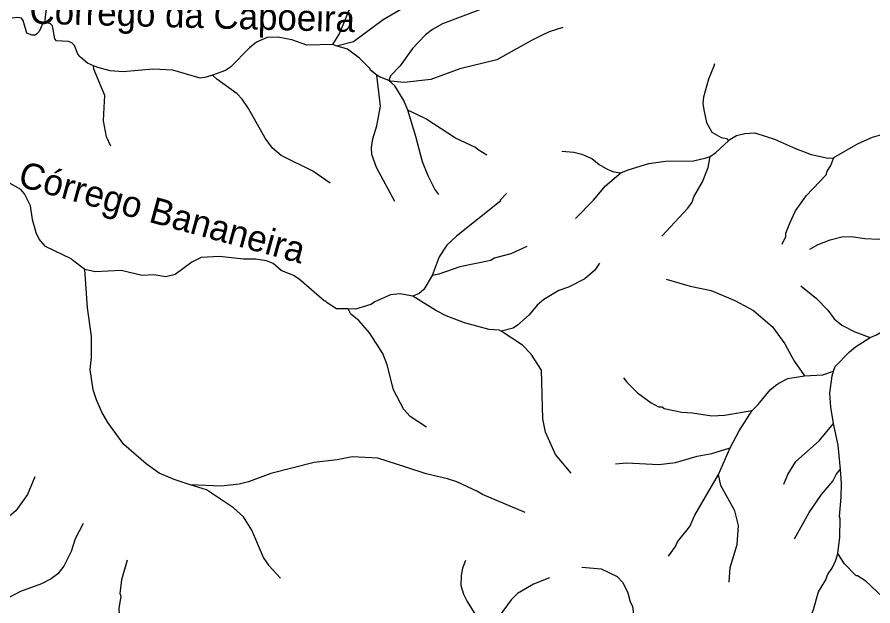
# Model space of a CAD drawing. Extents: x 393 to 446.6, y 8175.5 to 8231.
# Drawn here: x 415.52 to 420.77, y 8185.96 to 8189.58 of the extents above; entities that cross this region are included whole.
import ezdxf
from ezdxf.enums import TextEntityAlignment as Align

# ---------------------------------------------------------------- set-up
doc = ezdxf.new("R2010")
doc.units = 0
doc.header["$LTSCALE"] = 0.064
doc.linetypes.add('LONG_DASHED', pattern=[7.5, 6, -1.5])
doc.layers.add('61', color=7, linetype='Continuous')
doc.layers.add('7', color=7, linetype='Continuous', lineweight=25)
doc.layers.add('9', color=7, linetype='LONG_DASHED', lineweight=25)

msp = doc.modelspace()

# ---------------------------------------------------------------- linework, layer by layer
at = {"layer": '7'}
msp.add_line((419.8216, 8186.7653), (419.8938, 8186.9294), dxfattribs=at)
for points in [[(420.5309, 8188.7124), (420.6804, 8188.7995), (420.7676, 8188.8383), (421.0405, 8188.9158), (421.1244, 8188.9658), (421.1583, 8189.0159), (421.1729, 8189.0676), (421.1712, 8189.1903), (421.1793, 8189.2485), (421.2229, 8189.3421), (421.2423, 8189.3583), (421.2827, 8189.3776), (421.3678, 8189.3867)], [(419.7982, 8189.2882), (419.7926, 8189.2738), (419.7615, 8189.1936), (419.7292, 8189.0838), (419.726, 8189.045), (419.7325, 8189.0063), (419.7486, 8188.9287), (419.7809, 8188.869), (419.8391, 8188.8367), (419.8713, 8188.8302), (419.8827, 8188.8153)], [(419.8827, 8188.8153), (419.8911, 8188.8229), (419.9327, 8188.848), (419.9844, 8188.8609), (420.0441, 8188.8641), (420.115, 8188.8414), (420.1653, 8188.8254), (420.2944, 8188.7672), (420.3913, 8188.7317), (420.4947, 8188.7091), (420.5291, 8188.7113), (420.5309, 8188.7124)], [(419.7704, 8188.7194), (419.8051, 8188.7446), (419.8827, 8188.8153)], [(418.8595, 8188.7509), (418.9332, 8188.7463), (418.9832, 8188.7333), (419.0446, 8188.7059), (419.0898, 8188.6704), (419.1415, 8188.6397), (419.1802, 8188.6251), (419.2214, 8188.6181)], [(419.2214, 8188.6181), (419.2674, 8188.6381), (419.3934, 8188.6768), (419.4967, 8188.6897), (419.6679, 8188.693), (419.7454, 8188.7107), (419.7704, 8188.7194)], [(419.4748, 8188.23), (419.634, 8188.4023), (419.6598, 8188.4394), (419.6711, 8188.4717), (419.7228, 8188.5638), (419.7583, 8188.651), (419.7704, 8188.7194)], [(420.2133, 8188.1797), (420.2347, 8188.2279), (420.2363, 8188.2473), (420.2589, 8188.3087), (420.2944, 8188.3862), (420.3606, 8188.4766), (420.4834, 8188.6074), (420.4882, 8188.6284), (420.5124, 8188.6639), (420.5309, 8188.7123), (420.5309, 8188.7124)], [(420.383, 8188.1491), (420.4333, 8188.1779), (420.5076, 8188.2069), (420.5786, 8188.2247), (420.6368, 8188.2279), (420.7207, 8188.215), (420.8047, 8188.2117), (420.8564, 8188.2182), (420.9274, 8188.2505), (420.9791, 8188.2973), (421.0276, 8188.3248), (421.1567, 8188.3603), (421.1971, 8188.3845), (421.2601, 8188.4637), (421.2843, 8188.5121), (421.2988, 8188.5993), (421.3198, 8188.6381), (421.3441, 8188.6607), (421.3796, 8188.6736), (421.4715, 8188.6921), (421.4745, 8188.6927)], [(418.9446, 8188.3386), (419.0543, 8188.4507), (419.1285, 8188.5396), (419.2214, 8188.6181)], [(419.5012, 8187.9648), (419.6485, 8187.9227), (419.7777, 8187.8952), (419.923, 8187.8339), (420.0361, 8187.7725), (420.1539, 8187.6724), (420.2282, 8187.5675), (420.2717, 8187.4888), (420.288, 8187.4593), (420.35, 8187.3713)], [(420.328, 8187.924), (420.4236, 8187.8468), (420.493, 8187.7742), (420.5318, 8187.7225), (420.5786, 8187.6821), (420.6594, 8187.6417), (420.7534, 8187.608)], [(420.7534, 8187.608), (420.7918, 8187.6232), (420.8828, 8187.6759)], [(420.528, 8187.3995), (420.5381, 8187.4297), (420.6271, 8187.519), (420.6626, 8187.5497), (420.7534, 8187.608)], [(420.35, 8187.3713), (420.4624, 8187.3785), (420.5276, 8187.3994), (420.528, 8187.3995)], [(420.527, 8187.0789), (420.5124, 8187.1783), (420.5059, 8187.2655), (420.5189, 8187.3721), (420.528, 8187.3995)], [(419.239, 8187.36), (419.2594, 8187.3317), (419.3256, 8187.2671), (419.4095, 8187.2057), (419.4531, 8187.1815), (419.4757, 8187.1815), (419.4886, 8187.1718), (419.5969, 8187.1476), (419.6614, 8187.1444), (419.7809, 8187.125), (419.8584, 8187.1298), (420.028, 8187.1578)], [(420.028, 8187.1578), (420.0664, 8187.1962), (420.141, 8187.2881), (420.1803, 8187.3175), (420.1927, 8187.3268), (420.2476, 8187.3543), (420.35, 8187.3713)], [(419.8938, 8186.9294), (419.9488, 8187.033), (420.028, 8187.1578)], [(420.2232, 8186.7057), (420.2476, 8186.7649), (420.296, 8186.8456), (420.4398, 8186.9716), (420.527, 8187.0789)], [(420.57, 8186.7965), (420.5576, 8186.9458), (420.527, 8187.0789)], [(419.1892, 8186.8314), (419.2579, 8186.8372), (419.4547, 8186.8263), (419.5581, 8186.8392), (419.6905, 8186.8779), (419.7809, 8186.8941), (419.8938, 8186.9294)], [(419.5147, 8186.2636), (419.5581, 8186.3241), (419.5694, 8186.3515), (419.6469, 8186.4452), (419.676, 8186.5162), (419.8216, 8186.7653)], [(419.8882, 8186.1042), (419.8939, 8186.1933), (419.9359, 8186.3354), (419.944, 8186.4517), (419.9214, 8186.5421), (419.8358, 8186.6971), (419.8216, 8186.7653)], [(420.2884, 8186.3697), (420.3784, 8186.5324), (420.4543, 8186.6422), (420.5237, 8186.7245), (420.5447, 8186.7649), (420.5697, 8186.7961), (420.57, 8186.7965)], [(420.5543, 8186.281), (420.5673, 8186.3806), (420.5689, 8186.4936), (420.5641, 8186.5082), (420.5754, 8186.626), (420.577, 8186.7132), (420.57, 8186.7965)], [(415.6246, 8186.7521), (415.5792, 8186.6422), (415.5082, 8186.5421), (415.3887, 8186.4435), (415.3063, 8186.358), (415.1773, 8186.1552)], [(415.9215, 8186.4638), (415.8731, 8186.3709), (415.8473, 8186.2934), (415.8021, 8186.203), (415.7649, 8186.1561), (415.7246, 8186.1238), (415.6664, 8186.0931), (415.5373, 8186.0463), (415.4501, 8186.0011), (415.3629, 8185.972), (415.2854, 8185.9623), (415.1174, 8185.972), (415.0765, 8185.964)], [(416.1918, 8186.2392), (416.1573, 8186.1174), (416.1476, 8186.0512), (416.146, 8186.035), (416.1525, 8186.0173), (416.1412, 8185.9414), (416.1476, 8185.7864), (416.1379, 8185.7088), (416.104, 8185.5926), (416.0911, 8185.5667), (416.019, 8185.4685), (416.0187, 8185.4681)], [(420.3842, 8185.4635), (420.3558, 8185.5441), (420.3461, 8185.641), (420.3477, 8185.6943), (420.3752, 8185.8187), (420.3752, 8185.8541), (420.4058, 8185.9365), (420.4365, 8186.0447), (420.4817, 8186.119), (420.4914, 8186.1481), (420.5221, 8186.1949), (420.5415, 8186.2401), (420.5543, 8186.281)], [(421.0637, 8186.0792), (421.0404, 8186.0334), (420.9969, 8185.9849), (420.9371, 8185.9591), (420.8951, 8185.9672), (420.8289, 8186.014), (420.7255, 8186.1093), (420.6755, 8186.1432), (420.6674, 8186.1432), (420.5964, 8186.2175), (420.5543, 8186.281)]]:
    msp.add_lwpolyline(points, dxfattribs=at)
at = {"layer": '9'}
msp.add_line((417.4817, 8189.3978), (417.4516, 8189.4067), dxfattribs=at)
for points in [[(416.071, 8190.339), (416.0439, 8190.3239), (416.0065, 8190.2107), (415.9522, 8190.1754), (415.9119, 8190.1172), (415.9135, 8190.0494), (415.9054, 8190.0155), (415.8182, 8189.9428), (415.8085, 8189.8992), (415.7472, 8189.8201), (415.7455, 8189.7975), (415.7713, 8189.7849), (415.7713, 8189.7639), (415.7573, 8189.7371), (415.7095, 8189.6799), (415.6966, 8189.6426), (415.6861, 8189.5586), (415.6889, 8189.5437)], [(417.9643, 8190.06), (417.9619, 8190.0567), (417.911, 8189.9848), (417.8173, 8189.8911), (417.6219, 8189.7232), (417.5654, 8189.6457), (417.4945, 8189.4761), (417.4516, 8189.4067)], [(418.2612, 8189.9581), (418.2191, 8189.8742), (418.1853, 8189.8333), (418.1211, 8189.7738), (418.0657, 8189.7476), (417.9839, 8189.6904), (417.7624, 8189.5585), (417.5813, 8189.4237), (417.4843, 8189.3985), (417.4817, 8189.3978)], [(418.5923, 8189.7154), (418.5877, 8189.7134), (418.3987, 8189.6311), (418.3599, 8189.6215), (418.1274, 8189.5343), (418.066, 8189.4987), (418.0224, 8189.4665), (417.9433, 8189.3825), (417.8672, 8189.2751), (417.8089, 8189.2156), (417.7981, 8189.1861)], [(415.6889, 8189.5437), (415.6738, 8189.5382), (415.6503, 8189.4875), (415.6357, 8189.4713), (415.6261, 8189.4648), (415.6083, 8189.4648), (415.5744, 8189.4761), (415.5534, 8189.5536), (415.5421, 8189.5682), (415.5179, 8189.573), (415.486, 8189.5685)], [(415.9857, 8189.2768), (415.9472, 8189.2924), (415.9064, 8189.3263), (415.9019, 8189.3321), (415.8892, 8189.3486), (415.868, 8189.4017), (415.8521, 8189.418), (415.8321, 8189.4259), (415.7568, 8189.4293), (415.748, 8189.4418), (415.7334, 8189.5219), (415.7217, 8189.5347), (415.6889, 8189.5437)], [(418.8661, 8189.5121), (418.7814, 8189.4842), (418.7398, 8189.4643), (418.6732, 8189.4325), (418.46, 8189.313), (418.234, 8189.2581), (418.0563, 8189.1919), (417.8916, 8189.1742), (417.8094, 8189.1818), (417.7981, 8189.1861)], [(417.4516, 8189.4067), (417.2946, 8189.4038), (417.2018, 8189.4358), (417.1165, 8189.4519), (417.0519, 8189.4503), (416.9857, 8189.4212), (416.9421, 8189.3873), (416.8259, 8189.2678), (416.7952, 8189.2468), (416.716, 8189.2197)], [(417.7247, 8189.2197), (417.6849, 8189.2501), (417.6817, 8189.2598), (417.6171, 8189.3227), (417.5444, 8189.3793), (417.4817, 8189.3978)], [(416.0909, 8188.782), (416.0653, 8188.8399), (416.0459, 8188.9384), (416.0501, 8189.0194), (416.054, 8189.0935), (415.9877, 8189.2549), (415.9857, 8189.2768)], [(416.716, 8189.2197), (416.6682, 8189.2034), (416.6401, 8189.2), (416.4722, 8189.2501), (416.3511, 8189.2549), (416.167, 8189.2388), (416.0879, 8189.2452), (416.012, 8189.2662), (415.9857, 8189.2768)], [(417.4378, 8188.5556), (417.3313, 8188.6284), (417.1375, 8188.7253), (417.0842, 8188.7705), (417.039, 8188.8319), (416.9357, 8189.0143), (416.8969, 8189.0708), (416.8662, 8189.1047), (416.7419, 8189.1935), (416.7183, 8189.2174), (416.716, 8189.2197)], [(417.8338, 8188.4423), (417.7218, 8188.6522), (417.6944, 8188.7309), (417.6909, 8188.7741), (417.7002, 8188.8277), (417.7237, 8188.9077), (417.7465, 8189.0287), (417.7248, 8189.2185), (417.7247, 8189.2197)], [(417.7981, 8189.1861), (417.7399, 8189.208), (417.7247, 8189.2197)], [(417.9144, 8189.0045), (417.8899, 8189.0629), (417.8339, 8189.1538), (417.7981, 8189.1861)], [(418.3997, 8188.7263), (418.3454, 8188.7592), (418.3292, 8188.7753), (418.2081, 8188.8318), (418.0257, 8188.9508), (417.9144, 8189.0045)], [(418.1052, 8188.4848), (418.0807, 8188.5174), (418.0386, 8188.6009), (418.0046, 8188.6865), (417.9643, 8188.8415), (417.9144, 8189.0045)], [(415.9311, 8188.0253), (415.8564, 8188.0823), (415.8471, 8188.0894), (415.6906, 8188.1665), (415.6519, 8188.2118), (415.6325, 8188.2505), (415.6099, 8188.3313), (415.5986, 8188.4168), (415.5614, 8188.4895), (415.5388, 8188.517), (415.4452, 8188.5686), (415.4045, 8188.5995)], [(418.5194, 8188.4913), (418.482, 8188.4505), (418.4859, 8188.4459), (418.213, 8188.2295), (418.1532, 8188.1746), (418.1064, 8188.102), (418.0643, 8187.9885)], [(418.6461, 8188.1655), (418.5472, 8188.1213), (418.4439, 8188.0939), (418.4245, 8188.0809), (418.234, 8188.0406), (418.1053, 8187.9956), (418.0643, 8187.9885)], [(417.5482, 8187.7823), (417.4764, 8187.7842), (417.4134, 8187.8238), (417.4104, 8187.8307), (417.4007, 8187.8323), (417.2473, 8187.9647), (417.2118, 8187.9873), (417.1359, 8188.018), (417.0874, 8188.0616), (417.0471, 8188.0777), (416.9809, 8188.089), (416.9066, 8188.089), (416.758, 8188.1052), (416.6466, 8188.0987), (416.5877, 8188.0696), (416.4851, 8187.9938), (416.4286, 8187.9792), (416.3559, 8187.9922), (416.2833, 8187.9873), (416.1541, 8188.018), (415.9959, 8188.0099), (415.9311, 8188.0253)], [(416.5788, 8186.7019), (416.4803, 8186.7342), (416.3882, 8186.773), (416.3075, 8186.8311), (416.1718, 8186.9506), (416.0733, 8187.0846), (416.0362, 8187.1476), (416.0039, 8187.2235), (415.9829, 8187.2849), (415.9635, 8187.4108), (415.9716, 8187.4851), (415.9716, 8187.6143), (415.9474, 8187.7887), (415.9311, 8188.0253)], [(419.0914, 8188.0646), (419.0628, 8188.0209), (419.0021, 8187.9684), (418.9006, 8187.9159), (418.8411, 8187.8952), (418.7491, 8187.8403), (418.7087, 8187.8064), (418.6602, 8187.7467), (418.5876, 8187.6821), (418.5618, 8187.6643), (418.4899, 8187.6459), (418.4876, 8187.6453)], [(418.0643, 8187.9885), (418.0118, 8187.9022), (417.9849, 8187.8777), (417.945, 8187.8606)], [(417.945, 8187.8606), (417.8657, 8187.8746), (417.8073, 8187.8687), (417.7151, 8187.8279), (417.6883, 8187.8104), (417.5926, 8187.7812), (417.5482, 8187.7823)], [(418.4876, 8187.6453), (418.4759, 8187.6529), (418.4148, 8187.6562), (418.263, 8187.6982), (418.15, 8187.7402), (418.087, 8187.7726), (417.945, 8187.8606)], [(418.0288, 8187.0562), (417.9285, 8187.1226), (417.8894, 8187.1652), (417.827, 8187.2849), (417.7867, 8187.4399), (417.7608, 8187.5093), (417.68, 8187.6353), (417.6139, 8187.7112), (417.5654, 8187.7499), (417.5494, 8187.7801), (417.5482, 8187.7823)], [(418.9169, 8186.7728), (418.8217, 8186.8876), (418.7588, 8187.0249), (418.743, 8187.1083), (418.7346, 8187.406), (418.671, 8187.5057), (418.6183, 8187.561), (418.4876, 8187.6453)], [(418.6343, 8186.5327), (418.3728, 8186.6422), (418.3421, 8186.6615), (418.2146, 8186.7197), (418.1581, 8186.7391), (418.0273, 8186.7697), (417.9027, 8186.8097), (417.7301, 8186.865), (417.5719, 8186.8747), (417.4815, 8186.8553), (417.3394, 8186.8392), (417.0729, 8186.7714), (416.9357, 8186.7197), (416.8791, 8186.7068), (416.7677, 8186.6938), (416.5788, 8186.7019)], [(417.1323, 8186.1294), (417.0622, 8186.2071), (417.0616, 8186.2078), (417.0277, 8186.2562), (416.9566, 8186.4242), (416.9049, 8186.5049), (416.8436, 8186.5614), (416.6786, 8186.672), (416.5788, 8186.7019)], [(418.2678, 8186.2367), (418.2503, 8186.19), (418.2421, 8186.1445), (418.2409, 8186.0839), (418.2566, 8186.0302), (418.2791, 8185.985), (418.3486, 8185.8719), (418.3679, 8185.8073), (418.3743, 8185.7545)], [(418.9823, 8186.1969), (419.1011, 8186.1852), (419.1996, 8186.1384), (419.2351, 8186.1012), (419.2658, 8186.0383), (419.2804, 8185.9834), (419.2949, 8185.9559), (419.3224, 8185.7129), (419.3387, 8185.6569)], [(418.7842, 8186.1314), (418.687, 8186.092), (418.5876, 8186.035), (418.5488, 8185.9946), (418.4971, 8185.9268), (418.3938, 8185.7718), (418.3743, 8185.7545)]]:
    msp.add_lwpolyline(points, dxfattribs=at)

# ---------------------------------------------------------------- texts
at = {"layer": '61'}
for s, rotation, p in [('Córrego da Capoeira', 358.492, (416.5892, 8189.5095)), ('Córrego Bananeira', 344.65, (416.3861, 8188.2999))]:
    msp.add_text(s, height=0.16, rotation=rotation, dxfattribs=at).set_placement(p, align=Align.CENTER)

doc.saveas('drawing.dxf')
